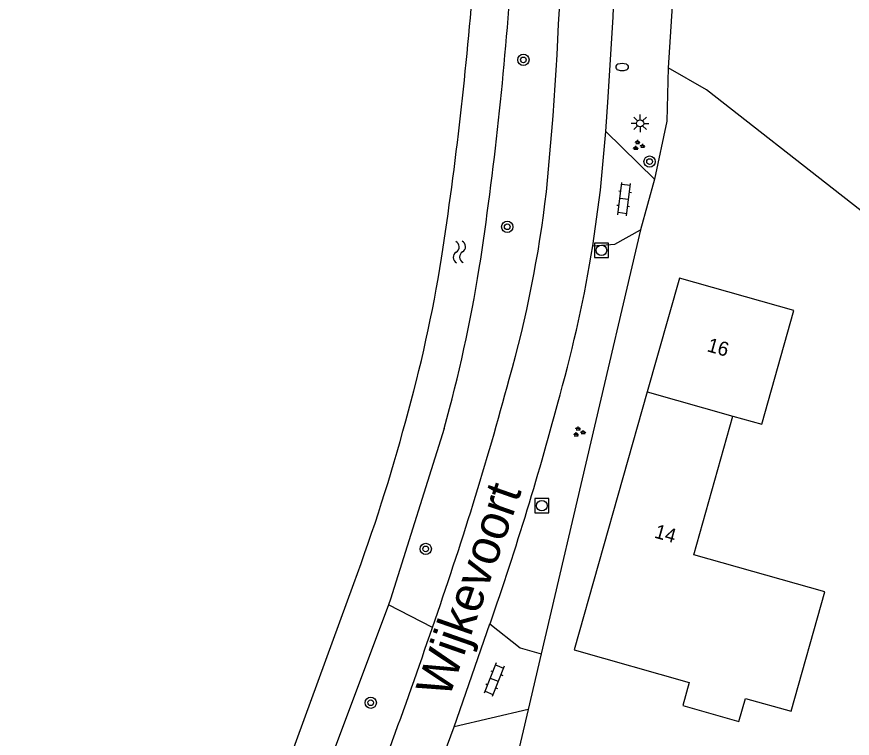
# Model space of a CAD drawing. Extents: x 124000 to 129000, y 395500 to 397503.
# Drawn here: x 125353.6 to 125412.6, y 396570.8 to 396621.7 of the extents above; entities that cross this region are included whole.
import ezdxf

# ---------------------------------------------------------------- set-up
doc = ezdxf.new("R2010")
doc.units = 0
for name, color, linetype in [('gg-anno-huisnummerreeks BGT', 7, 'Continuous'), ('gg-anno-openbare ruimte label', 7, 'Continuous'), ('gg-bbg-gedigitaliseerde bebouwing', 7, 'Continuous'), ('gg-bbg-hoofdgebouw', 7, 'Continuous'), ('gg-bbg-tussenscheiding', 7, 'Continuous'), ('gg-knt-bronhoudergrens', 7, 'Continuous'), ('gg-knt-verharding', 7, 'Continuous'), ('gg-kntw-bovenkant insteek waterloop', 7, 'Continuous'), ('gt-grn-groengrens', 7, 'Continuous'), ('gt-grn-weggrens', 7, 'Continuous'), ('gt-symb-boom', 7, 'Continuous'), ('gt-symb-brandkraan', 7, 'Continuous'), ('gt-symb-groenvak', 7, 'Continuous'), ('gt-symb-klinker verharding', 7, 'Continuous'), ('gt-symb-lichtmast', 7, 'Continuous'), ('gt-symb-rioolschacht', 7, 'Continuous'), ('gt-symb-watersymbool', 7, 'Continuous')]:
    doc.layers.add(name, color=color, linetype=linetype)

# ---------------------------------------------------------------- blocks, each defined once
blk = doc.blocks.new('gt0-BR')
at = {"layer": 'gt-symb-brandkraan'}
for centre, radius, start, end in [((-0.244, 0), 0.206, 107.56694, 252.43307), ((0.599, -2.664), 3, 106.89205, 107.56694), ((0, -0.691), 0.938, 73.10799, 106.89205), ((-0.599, -2.664), 3, 72.43309, 73.10799), ((0.244, 0), 0.206, 287.56695, 72.43309), ((0.599, 2.664), 3, 252.43307, 253.10797), ((0, 0.691), 0.938, 253.10797, 286.89206), ((-0.599, 2.664), 3, 286.89206, 287.56695)]:
    blk.add_arc(centre, radius, start, end, dxfattribs=at)
blk = doc.blocks.new('gt0-RS')
at = {"layer": 'gt-symb-rioolschacht'}
blk.add_lwpolyline([(-0.5, -0.5), (0.5, -0.5), (0.5, 0.5), (-0.5, 0.5)], close=True, dxfattribs=at)
blk.add_circle((0, 0), 0.375, dxfattribs=at)
blk = doc.blocks.new('gt0-GRVAK')
at = {"layer": 'gt-symb-groenvak'}
for p, q in [((-0.11, 0.189), (-0.228, 0.24)), ((-0.182, 0.153), (0.088, 0.153)), ((-0.091, 0.211), (-0.156, 0.322)), ((-0.047, 0.214), (-0.047, 0.393)), ((-0.004, 0.211), (0.061, 0.322)), ((0.015, 0.189), (0.133, 0.24)), ((0.262, -0.052), (0.197, 0.059)), ((0.305, -0.049), (0.305, 0.13)), ((0.349, -0.052), (0.414, 0.059)), ((-0.245, -0.228), (-0.363, -0.177)), ((-0.318, -0.264), (-0.047, -0.264)), ((-0.226, -0.206), (-0.291, -0.095)), ((-0.183, -0.203), (-0.183, -0.024)), ((-0.139, -0.206), (-0.074, -0.095)), ((-0.12, -0.228), (-0.002, -0.177)), ((0.243, -0.074), (0.125, -0.023)), ((0.17, -0.11), (0.441, -0.11)), ((0.368, -0.074), (0.486, -0.023))]:
    blk.add_line(p, q, dxfattribs=at)
blk = doc.blocks.new('gt0-WA')
at = {"layer": 'gt-symb-watersymbool'}
for centre, start, end in [((-0.323, 0.022), 28.07249, 151.92751), ((0.427, 0.422), 208.07248, 331.92751), ((-0.323, -0.428), 28.07249, 151.92751), ((0.427, -0.028), 208.07248, 331.92751)]:
    blk.add_arc(centre, 0.425, start, end, dxfattribs=at)
blk = doc.blocks.new('gt0-BOOM')
at = {"layer": 'gt-symb-boom'}
for radius in [0.4, 0.2]:
    blk.add_circle((0, 0), radius, dxfattribs=at)
blk = doc.blocks.new('gt0-KL1')
at = {"layer": 'gt-symb-klinker verharding'}
for p, q in [((-1.15, 0.3), (1.15, 0.3)), ((-1, -0.3), (-1, 0.3)), ((-0.5, 0.3), (-0.5, 0.45)), ((0, -0.3), (0, 0.3)), ((0.5, 0.3), (0.5, 0.45)), ((1, -0.3), (1, 0.3)), ((-1.15, -0.3), (1.15, -0.3)), ((-0.5, -0.45), (-0.5, -0.3)), ((0.5, -0.45), (0.5, -0.3))]:
    blk.add_line(p, q, dxfattribs=at)
blk = doc.blocks.new('gt0-LMAST')
at = {"layer": 'gt-symb-lichtmast'}
for p, q in [((-0.005, 0.246), (-0.005, 0.621)), ((-0.182, 0.173), (-0.447, 0.438)), ((0.172, 0.173), (0.437, 0.438)), ((-0.255, -0.004), (-0.63, -0.004)), ((-0.182, -0.181), (-0.447, -0.446)), ((-0.005, -0.254), (-0.005, -0.629)), ((0.437, -0.446), (0.172, -0.181)), ((0.245, -0.004), (0.62, -0.004))]:
    blk.add_line(p, q, dxfattribs=at)
blk.add_circle((-0.005, -0.004), 0.25, dxfattribs=at)

msp = doc.modelspace()

# ---------------------------------------------------------------- linework, layer by layer
at = {"layer": 'gg-bbg-gedigitaliseerde bebouwing'}
for points in [[(125404.143, 396593.509), (125406.183, 396592.934), (125408.443, 396600.953), (125400.37, 396603.23)], [(125408.272, 396572.672), (125410.649, 396581.107), (125401.384, 396583.718), (125404.143, 396593.509)]]:
    msp.add_lwpolyline(points, dxfattribs=at)
at = {"layer": 'gg-bbg-hoofdgebouw'}
for p, q in [((125400.37, 396603.23), (125398.103, 396595.215)), ((125398.103, 396595.215), (125392.95, 396577))]:
    msp.add_line(p, q, dxfattribs=at)
msp.add_lwpolyline([(125392.95, 396577), (125401.064, 396574.708), (125400.603, 396573.077), (125404.577, 396571.949), (125405.039, 396573.586), (125408.272, 396572.672)], dxfattribs=at)
at = {"layer": 'gg-bbg-tussenscheiding'}
msp.add_line((125398.103, 396595.215), (125404.143, 396593.509), dxfattribs=at)
at = {"layer": 'gg-knt-bronhoudergrens'}
msp.add_lwpolyline([(125489.775, 396533.26), (125484.986, 396542.913), (125441.725, 396567.519), (125449.774, 396581.67), (125445.576, 396586.975), (125433.199, 396596.601), (125421.55, 396601.47), (125402.296, 396616.539), (125399.58, 396618.082)], dxfattribs=at)
at = {"layer": 'gg-knt-verharding'}
for p, q in [((125395.338, 396616.002), (125395.7, 396621.69)), ((125395.185, 396613.588), (125395.338, 396616.002)), ((125398.609, 396610.223), (125395.185, 396613.588)), ((125384.47, 396571.584), (125386.999, 396578.838)), ((125389.7, 396572.811), (125384.47, 396571.584))]:
    msp.add_line(p, q, dxfattribs=at)
for points in [[(125394.257, 396605.518), (125394.809, 396609.457), (125395.185, 396613.588)], [(125394.257, 396605.518), (125395.82, 396605.644), (125397.632, 396606.654)], [(125386.999, 396578.838), (125389.139, 396577.159), (125390.62, 396576.733)], [(125367.783, 396527.734), (125371.63, 396538), (125382.43, 396566.048), (125384.47, 396571.584)]]:
    msp.add_lwpolyline(points, dxfattribs=at)
for centre, radius, start, end in [((125163.87, 396631.912), 228.23, 354.321, 2.98264), ((125170.642, 396631.87), 225.288, 357.41017, 359.94411), ((125308.067, 396618.906), 83.463, 344.1548, 353.41055), ((125299.434, 396620.855), 96.055, 344.39584, 350.81243), ((125148.82, 396660.723), 248.099, 340.66739, 344.90584), ((125175.573, 396652.371), 223.849, 340.82257, 345.15422), ((125080.046, 396680.803), 319.665, 338.1132, 341.3522)]:
    msp.add_arc(centre, radius, start, end, dxfattribs=at)
at = {"layer": 'gg-kntw-bovenkant insteek waterloop'}
for p, q in [((125353.581, 396516.68), (125377.377, 396581.694)), ((125379.833, 396580.188), (125355.72, 396515.907))]:
    msp.add_line(p, q, dxfattribs=at)
msp.add_lwpolyline([(125383.772, 396592.633), (125379.982, 396580.586), (125379.833, 396580.188)], dxfattribs=at)
for centre, radius, start, end in [((125119.566, 396644.85), 267.057, 351.34191, 355.68977), ((125144.369, 396640.713), 244.655, 351.35459, 356.28942), ((125280.706, 396621.268), 104.208, 344.35671, 350.82255), ((125279.302, 396621.401), 108.359, 344.60391, 350.72517), ((125255.071, 396627.212), 130.501, 339.58657, 344.8788)]:
    msp.add_arc(centre, radius, start, end, dxfattribs=at)
at = {"layer": 'gt-grn-groengrens'}
for p, q in [((125399.867, 396622.451), (125399.58, 396618.082)), ((125399.489, 396614.319), (125398.609, 396610.223)), ((125397.632, 396606.654), (125390.62, 396576.733)), ((125382.929, 396578.59), (125379.833, 396580.188)), ((125389.7, 396572.811), (125388.901, 396569.4))]:
    msp.add_line(p, q, dxfattribs=at)
at = {"layer": 'gt-grn-weggrens'}
for p, q in [((125399.58, 396618.082), (125399.489, 396614.319)), ((125398.609, 396610.223), (125397.632, 396606.654)), ((125390.62, 396576.733), (125389.7, 396572.811))]:
    msp.add_line(p, q, dxfattribs=at)

# ---------------------------------------------------------------- block references
at = {"layer": 'gt-symb-boom'}
for p in [(125389.354, 396618.645), (125398.268, 396611.468), (125388.218, 396606.863), (125382.46, 396584.133), (125378.575, 396573.276)]:
    msp.add_blockref('gt0-BOOM', p, dxfattribs=at)
at = {"layer": 'gt-symb-brandkraan'}
msp.add_blockref('gt0-BR', (125396.33, 396618.139), dxfattribs=at)
at = {"layer": 'gt-symb-groenvak'}
for p in [(125397.477, 396612.6), (125393.271, 396592.386)]:
    msp.add_blockref('gt0-GRVAK', p, dxfattribs=at)
at = {"layer": 'gt-symb-klinker verharding'}
for p, rotation in [((125396.473, 396608.82), 83.05258934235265), ((125387.296, 396574.905), -111.4820383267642)]:
    msp.add_blockref('gt0-KL1', p, dxfattribs=dict(at, rotation=rotation))
at = {"layer": 'gt-symb-lichtmast'}
msp.add_blockref('gt0-LMAST', (125397.605, 396614.167), dxfattribs=at)
at = {"layer": 'gt-symb-rioolschacht'}
for p in [(125394.867, 396605.205), (125390.655, 396587.184)]:
    msp.add_blockref('gt0-RS', p, dxfattribs=at)
at = {"layer": 'gt-symb-watersymbool', "rotation": -87.53533664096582}
msp.add_blockref('gt0-WA', (125384.838, 396605.141), dxfattribs=at)

# ---------------------------------------------------------------- texts
at = {"layer": 'gg-anno-huisnummerreeks BGT'}
for s, p in [('16', (125402.266, 396598.092)), ('14', (125398.546, 396584.942))]:
    msp.add_text(s, height=1, rotation=344.2, dxfattribs=at).set_placement(p)
at = {"layer": 'gg-anno-openbare ruimte label'}
msp.add_text('Wijkevoort', height=2.5, rotation=70.7, dxfattribs=at).set_placement((125384.085, 396573.499))

doc.saveas('drawing.dxf')
